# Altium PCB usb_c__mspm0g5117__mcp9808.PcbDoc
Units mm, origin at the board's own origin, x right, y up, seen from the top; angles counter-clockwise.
Board outline 68 x 40 mm, 2 copper layers (Top, Bottom), stack 0 mm thick; 35 components, 28 nets, 180 pads, 67 vias.
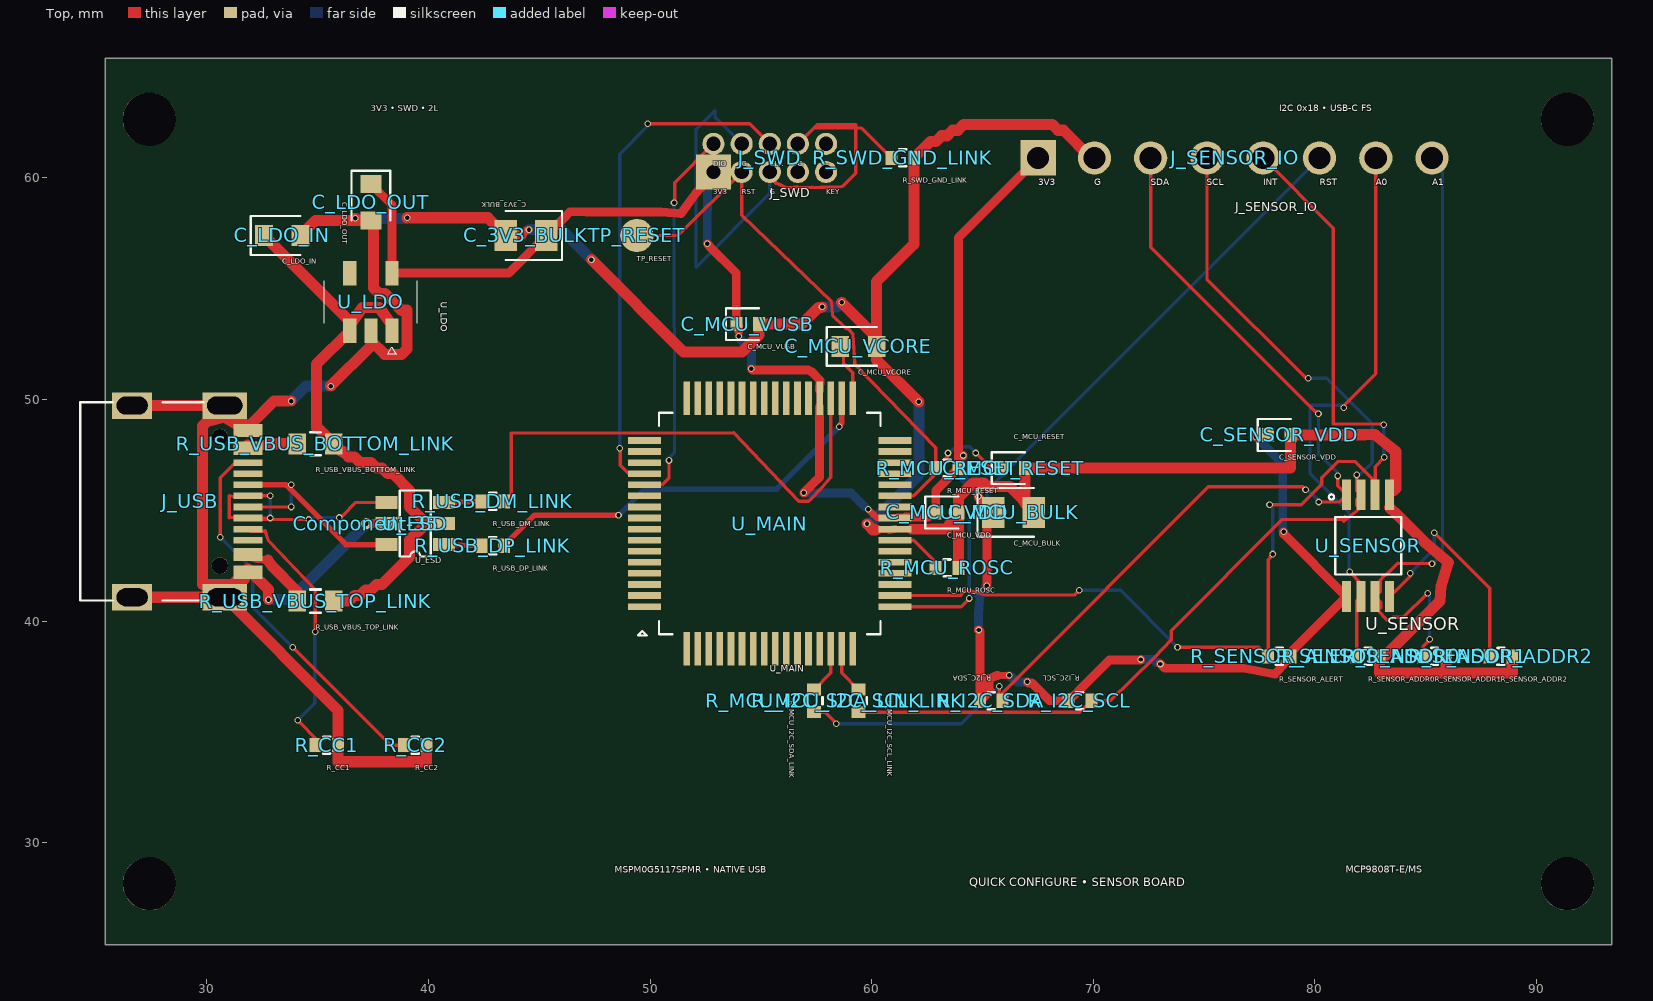
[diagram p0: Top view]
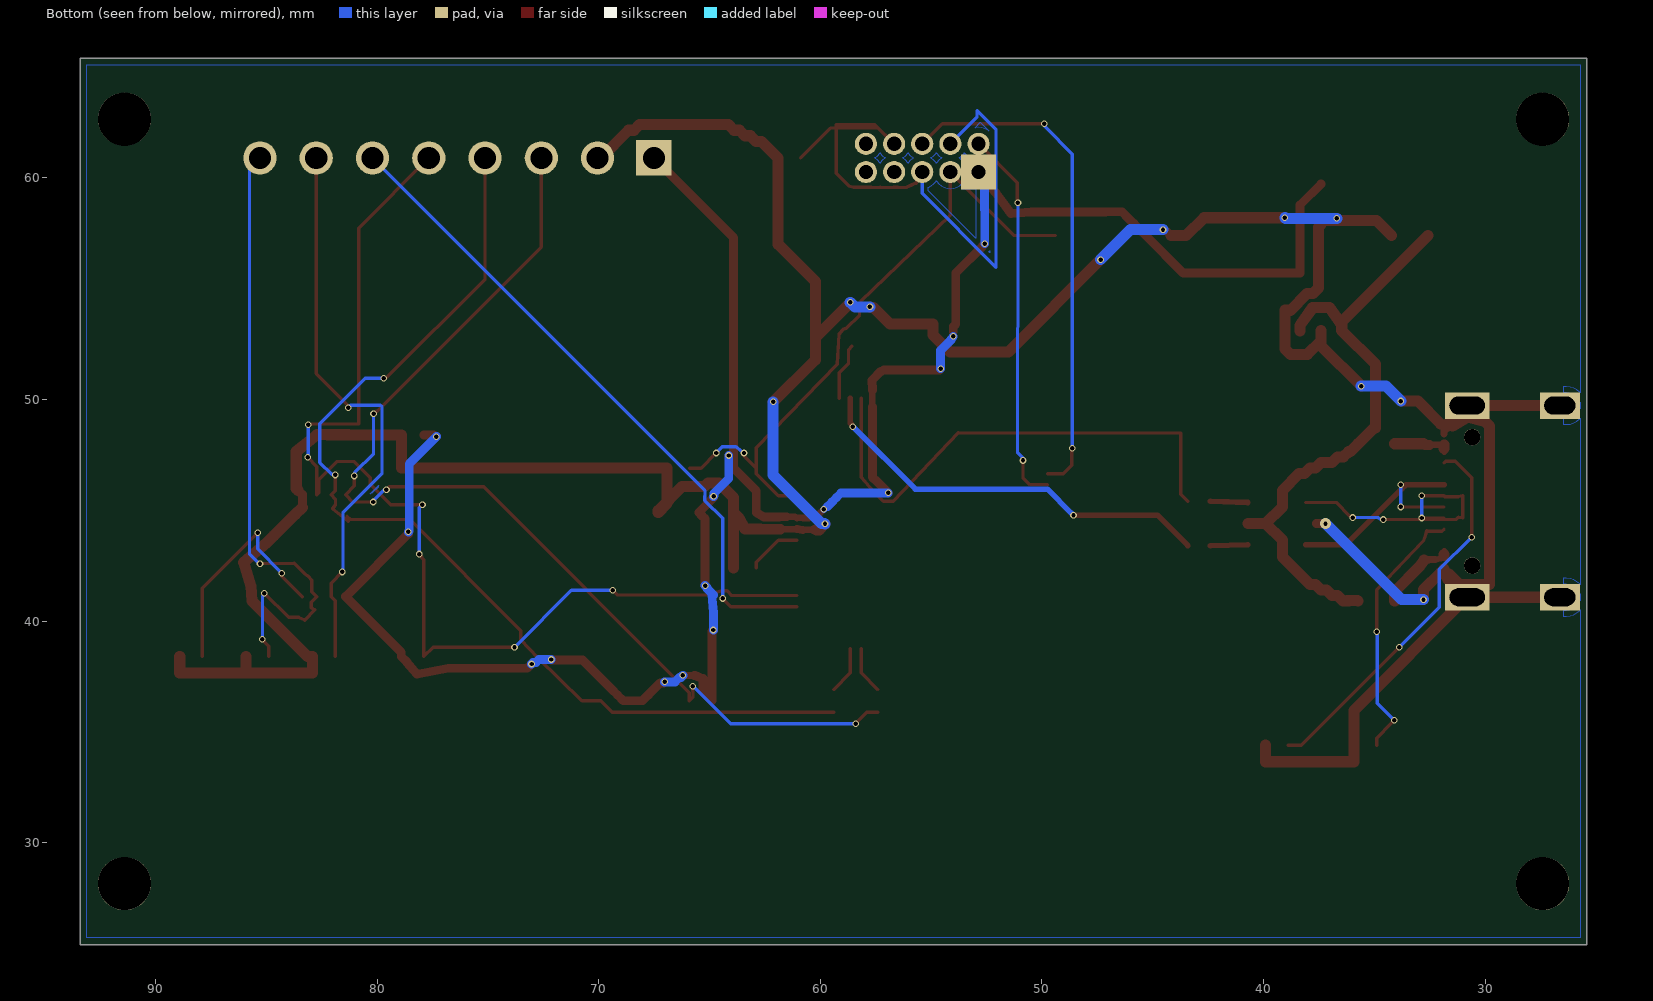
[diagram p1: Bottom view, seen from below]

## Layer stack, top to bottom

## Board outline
25.4,65.4 93.4,65.4 93.4,25.4 25.4,25.4

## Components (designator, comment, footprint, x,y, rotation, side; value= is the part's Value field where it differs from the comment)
C_3V3_BULK "" TSCIRCUIT-2.8500x1.4000mm 44.4,57.4 r180 top
C_LDO_IN "" TSCIRCUIT-2.4500x0.9500mm 33.4,57.4 r0 top
C_LDO_OUT "" TSCIRCUIT-0.9500x2.4500mm 37.4,58.9 r270 top
C_MCU_BULK "" TSCIRCUIT-2.8500x1.4000mm 66.4,44.9 r0 top
C_MCU_RESET "" TSCIRCUIT-1.5600x0.6400mm 66.4,46.9 r0 top
C_MCU_VCORE "" TSCIRCUIT-2.4500x0.9500mm 59.4,52.4 r0 top
C_MCU_VDD "" TSCIRCUIT-1.5600x0.6400mm 63.4,44.9 r0 top
C_MCU_VUSB "" TSCIRCUIT-1.5600x0.6400mm 54.4,53.4 r0 top
C_SENSOR_VDD "" TSCIRCUIT-1.5600x0.6400mm 78.4,48.4 r0 top
Component-35 "" TSCIRCUIT-0.5000x0.5000mm 37.2,44.4 r0 top
J_SENSOR_IO "" TSCIRCUIT-19.2800x1.5000mm 76.4,60.9 r0 top
J_SWD "" TSCIRCUIT-6.0800x2.2700mm 55.4,60.9 r0 top
J_USB "" TSCIRCUIT-6.7732x9.8502mm 29.112,45.4 r90 top
R_CC1 "" TSCIRCUIT-1.5600x0.6400mm 35.4,34.4 r0 top
R_CC2 "" TSCIRCUIT-1.5600x0.6400mm 39.4,34.4 r0 top
R_I2C_SCL "" TSCIRCUIT-1.5600x0.6400mm 69.4,36.4 r180 top
R_I2C_SDA "" TSCIRCUIT-1.5600x0.6400mm 65.4,36.4 r180 top
R_MCU_I2C_SCL_LINK "" TSCIRCUIT-0.6400x1.5600mm 59.4,36.4 r270 top
R_MCU_I2C_SDA_LINK "" TSCIRCUIT-0.6400x1.5600mm 57.4,36.4 r270 top
R_MCU_RESET "" TSCIRCUIT-1.5600x0.6400mm 63.4,46.9 r0 top
R_MCU_ROSC "" TSCIRCUIT-1.5600x0.6400mm 63.4,42.4 r0 top
R_SENSOR_ADDR0 "" TSCIRCUIT-1.5600x0.6400mm 82.4,38.4 r0 top
R_SENSOR_ADDR1 "" TSCIRCUIT-1.5600x0.6400mm 85.4,38.4 r0 top
R_SENSOR_ADDR2 "" TSCIRCUIT-1.5600x0.6400mm 88.4,38.4 r0 top
R_SENSOR_ALERT "" TSCIRCUIT-1.5600x0.6400mm 78.4,38.4 r0 top
R_SWD_GND_LINK "" TSCIRCUIT-1.5600x0.6400mm 61.4,60.9 r0 top
R_USB_DM_LINK "" TSCIRCUIT-1.5600x0.6400mm 42.9,45.4 r0 top
R_USB_DP_LINK "" TSCIRCUIT-1.5600x0.6400mm 42.9,43.4 r0 top
R_USB_VBUS_BOTTOM_LINK "" TSCIRCUIT-2.4500x0.9500mm 34.9,48 r0 top
R_USB_VBUS_TOP_LINK "" TSCIRCUIT-2.4500x0.9500mm 34.9,40.9 r0 top
TP_RESET "" TSCIRCUIT-1.5000x1.5000mm 49.4,57.4 r0 top
U_ESD "" TSCIRCUIT-3.6000x2.5000mm 39.4,44.4 r0 top
U_LDO "" TSCIRCUIT-2.5000x3.7000mm 37.4,54.4 r270 top
U_MAIN "" TSCIRCUIT-12.8000x12.8000mm 55.4,44.4 r0 top
U_SENSOR "" TSCIRCUIT-2.3562x5.9969mm 82.4,43.4 r0 top

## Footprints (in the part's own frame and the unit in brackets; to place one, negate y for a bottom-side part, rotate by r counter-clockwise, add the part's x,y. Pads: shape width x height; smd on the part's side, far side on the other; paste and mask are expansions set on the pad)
TSCIRCUIT-0.5000x0.5000mm [mm]
TSCIRCUIT-0.6400x1.5600mm [mm]
  rect 0.54x0.64 smd: 1(-0.51,0) 2(0.51,0)
  silkscreen extent -0.15,-0.38 0.15,0.38
TSCIRCUIT-0.9500x2.4500mm [mm]
  rect 0.8x0.95 smd: 1(-0.825,0) 2(0.825,0)
  silkscreen extent -1.43,-0.87 0.82,0.88
TSCIRCUIT-1.5000x1.5000mm [mm]
  round 1.5 smd: 1(0,0)
TSCIRCUIT-1.5600x0.6400mm [mm]
  rect 0.54x0.64 smd: 1(-0.51,0) 2(0.51,0)
  silkscreen extent -0.98,-0.72 0.51,0.72
TSCIRCUIT-2.3562x5.9969mm [mil]
  rect 15.98x55 smd: 1(-38.39,90.55) 2(-12.8,90.55) 3(12.8,90.55) 4(38.39,90.55) 5(38.39,-90.55) 6(12.8,-90.55) 7(-12.8,-90.55) 8(-38.39,-90.55)
  silkscreen extent -70,-51 59,91
TSCIRCUIT-2.4500x0.9500mm [mm]
  rect 0.8x0.95 smd: 1(-0.825,0) 2(0.825,0)
  silkscreen extent -1.42,-0.87 0.82,0.87
TSCIRCUIT-2.5000x3.7000mm [mm]
  rect 1.1x0.6 smd: 1(1.3,0.95) 2(1.3,0) 3(1.3,-0.95) 4(-1.3,-0.95) 5(-1.3,0.95)
  silkscreen extent -0.95,-2.1 2.35,2.1
TSCIRCUIT-2.8500x1.4000mm [mm]
  rect 1.025x1.4 smd: 1(-0.913,0) 2(0.913,0)
  silkscreen extent -1.63,-1.1 0.91,1.1
TSCIRCUIT-3.6000x2.5000mm [mm]
  rect 1x0.6 smd: 1(-1.3,-0.95) 2(-1.3,0) 3(-1.3,0.95) 4(1.3,0.95) 5(1.3,0) 6(1.3,-0.95)
  silkscreen extent -0.7,-1.49 0.7,1.49
TSCIRCUIT-6.0800x2.2700mm [mm]
  rect 1.6x1.6 hole 0.65: 1(-2.54,-0.635)
  round 1 hole 0.65: 2(-2.54,0.635) 3(-1.27,0.635) 4(0,0.635) 5(1.27,0.635) 6(2.54,0.635) 7(2.54,-0.635) 8(1.27,-0.635) 9(0,-0.635) 10(-1.27,-0.635)
TSCIRCUIT-6.7732x9.8502mm [mm]
  rect 0.3x1.3 smd: 1(-3.35,-2.737) 2(-3.05,-2.737) 3(-2.55,-2.737) 4(-2.25,-2.737) 5(-1.75,-2.737) 6(-1.25,-2.737) 7(-0.75,-2.737) 8(-0.25,-2.737) 9(0.25,-2.737) 10(0.75,-2.737) 11(1.25,-2.737) 12(1.75,-2.737) 13(2.55,-2.737) 14(2.25,-2.737) 15(3.35,-2.737) 16(3.05,-2.737)
  rect 1.2x2 hole 0.8 slot 1.6 at 90 deg: 17(-4.325,-1.693) 18(4.325,-1.693)
  rect 1.2x1.8 hole 0.8 slot 1.4 at 90 deg: 19(4.325,2.487) 20(-4.325,2.487)
  round 0.75 hole 0.75 unplated: NPTH-1(-2.9,-1.468) NPTH-2(2.9,-1.468)
  silkscreen extent -4.47,-0.75 4.47,4.83
TSCIRCUIT-12.8000x12.8000mm [mm]
  rect 1.5x0.3 smd: 1(-5.65,-3.75) 2(-5.65,-3.25) 3(-5.65,-2.75) 4(-5.65,-2.25) 5(-5.65,-1.75) 6(-5.65,-1.25) 7(-5.65,-0.75) 8(-5.65,-0.25) 9(-5.65,0.25) 10(-5.65,0.75) 11(-5.65,1.25) 12(-5.65,1.75) 13(-5.65,2.25) 14(-5.65,2.75) 15(-5.65,3.25) 16(-5.65,3.75) 33(5.65,3.75) 34(5.65,3.25) 35(5.65,2.75) 36(5.65,2.25) 37(5.65,1.75) 38(5.65,1.25) 39(5.65,0.75) 40(5.65,0.25) 41(5.65,-0.25) 42(5.65,-0.75) 43(5.65,-1.25) 44(5.65,-1.75) 45(5.65,-2.25) 46(5.65,-2.75) 47(5.65,-3.25) 48(5.65,-3.75)
  rect 0.3x1.5 smd: 17(-3.75,5.65) 18(-3.25,5.65) 19(-2.75,5.65) 20(-2.25,5.65) 21(-1.75,5.65) 22(-1.25,5.65) 23(-0.75,5.65) 24(-0.25,5.65) 25(0.25,5.65) 26(0.75,5.65) 27(1.25,5.65) 28(1.75,5.65) 29(2.25,5.65) 30(2.75,5.65) 31(3.25,5.65) 32(3.75,5.65) 49(3.75,-5.65) 50(3.25,-5.65) 51(2.75,-5.65) 52(2.25,-5.65) 53(1.75,-5.65) 54(1.25,-5.65) 55(0.75,-5.65) 56(0.25,-5.65) 57(-0.25,-5.65) 58(-0.75,-5.65) 59(-1.25,-5.65) 60(-1.75,-5.65) 61(-2.25,-5.65) 62(-2.75,-5.65) 63(-3.25,-5.65) 64(-3.75,-5.65)
  silkscreen extent -5.95,-5.05 5,5
TSCIRCUIT-19.2800x1.5000mm [mm]
  rect 1.6x1.6 hole 1: 1(-8.89,0)
  round 1.5 hole 1: 2(-6.35,0) 3(-3.81,0) 4(-1.27,0) 5(1.27,0) 6(3.81,0) 7(6.35,0) 8(8.89,0)

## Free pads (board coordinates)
  round 2.4 hole 2.4 unplated: NPTH-3(27.4,28.15) NPTH-4(91.4,28.15) NPTH-5(27.4,62.65) NPTH-6(91.4,62.65)

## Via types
v1: diameter 0.3, hole 0.2, Top to Bottom, 66 vias
v2: diameter 0.5, hole 0.2, Top to Bottom, 1 vias

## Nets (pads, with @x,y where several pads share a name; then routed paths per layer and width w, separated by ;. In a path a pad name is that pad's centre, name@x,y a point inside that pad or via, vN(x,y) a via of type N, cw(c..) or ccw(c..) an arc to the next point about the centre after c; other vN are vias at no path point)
".J_SWD > .pin2 to .U_MAIN > .pin12": J_SWD.2 U_MAIN.12 | length 17.2
  Top w0.15: U_MAIN.12 49.759,46.159 50.54,46.159 50.853,46.472 v1(50.853,47.247) ; v1(51.08,58.875) 51.105,58.856 51.105,59.012 51.105,59.78 J_SWD.2
  Bottom w0.15: v1(50.853,47.247) 50.793,47.307 51.102,47.616 v1(51.08,58.875)
".J_SWD > .pin4 to .U_MAIN > .pin13": J_SWD.4 U_MAIN.13 | length 23.1
  Top w0.15: v1(48.63,47.806) 48.64,47.796 48.64,47.769 48.656,47.753 48.656,47.026 49.032,46.65 U_MAIN.13 ; v1(49.886,62.448) 54.487,62.448 J_SWD.4
  Bottom w0.15: v1(48.63,47.806) 48.63,61.072 49.855,62.297 49.855,62.417 v1(49.886,62.448)
".U_MAIN > .pin42 to .R_MCU_ROSC > .pin1": R_MCU_ROSC.1 U_MAIN.42 | length 2.5
  Top w0.15: U_MAIN.42 61.89,43.65 62.89,42.65 R_MCU_ROSC.1
GND: C_3V3_BULK.2 C_LDO_IN.2 C_LDO_OUT.2 C_MCU_BULK.2 C_MCU_RESET.2 C_MCU_VCORE.2 C_MCU_VDD.2 C_MCU_VUSB.2 C_SENSOR_VDD.2 J_SENSOR_IO.2 J_USB.1 J_USB.2 J_USB.15 J_USB.16 J_USB.17 J_USB.18 J_USB.19 J_USB.20 R_CC1.2 R_CC2.2 R_MCU_ROSC.2 R_SENSOR_ADDR0.2 R_SENSOR_ADDR1.2 R_SENSOR_ADDR2.2 R_SWD_GND_LINK.2 U_ESD.2 U_LDO.2 U_MAIN.41 U_SENSOR.4 | length 177.8
  Top w0.275: J_USB.15@31.467,48.8 31.8,48.6 J_USB.16 ; J_USB.1@31.624,42.125 J_USB.2
  Top w0.3: J_USB.1@31.699,41.9 J_USB.1 J_USB.1@31.849,42.2 ; J_USB.15@31.699,48.9 J_USB.15 ; J_USB.2 J_USB.1@31.999,42.2 ; J_USB.16@31.849,48.6 J_USB.15 ; J_USB.15@31.999,48.9 J_USB.15 ; 60.3,44.12 60.425,44.12 60.55,44.12 60.675,44.12 U_MAIN.41@60.796,44.111 ; U_MAIN.41 61.144,44.15 61.238,44.15 61.331,44.15 61.425,44.15 61.519,44.15 61.613,44.15 61.706,44.15 61.8,44.15
  Top w0.325: J_USB.16 J_USB.16@31.849,48.6 ; v1@44.396,57.621 44.502,57.621 v1(44.535,57.666)
  Top w0.375: 44.175,57.4 v1@44.396,57.621 ; U_MAIN.41@60.796,44.111 U_MAIN.41
  Top w0.4: 37.2,44.4 U_ESD.2@37.6,44.4 ; 60.175,44.12 60.3,44.12
  Top w0.406: U_SENSOR.4@83.375,45.129 83.375,45.414 U_SENSOR.4 83.578,45.903
  Top w0.475: 61.8,44.15 62.253,44.15 62.707,44.15
  Top w0.5: J_USB.20 J_USB.17 ; J_USB.19 J_USB.18 ; J_USB.18 30.874,49.725 31.474,49.125 31.699,48.9 ; J_USB.15@31.467,48.8 31.133,49 30.8,49.2 30,49 29.8,48.8 29.8,41.65 31.15,41.65 J_USB.1@31.624,42.124 ; 31.699,41.9 31.474,41.675 30.874,41.075 J_USB.17 35.91,35.971 R_CC1.2 35.91,33.65 39.91,33.65 R_CC2.2 ; J_USB.1@31.849,42.2 J_USB.2 ; J_USB.1@31.999,42.2 32.778,41.421 v1(32.778,40.965) ; 31.999,48.9 33.028,49.929 v1(33.802,49.929) ; C_LDO_IN.2 34.9,58.075 C_LDO_OUT.2 ; v1(35.586,50.6) 37.4,52.414 U_LDO.2 37.4,52.65 38.025,52.025 38.775,52.025 39.025,52.275 39.025,54.025 38.775,54.025 38.025,54.775 37.775,54.775 37.525,55.025 37.525,57.775 37.4,57.9 C_LDO_OUT.2 ; v1(36.694,58.171) 36.781,58.084 36.9,58.084 36.91,58.075 C_LDO_OUT.2 ; v1(39.034,58.199) 42.688,58.199 C_3V3_BULK.2 43.831,57.4 44.175,57.4 ; v1(47.353,56.313) 51.516,52.15 54.15,52.15 54.91,52.91 C_MCU_VUSB.2 55.398,53.4 55.885,53.4 56.373,53.4 56.86,53.4 57.108,53.647 57.355,53.895 57.602,54.142 57.725,54.142 v1(57.76,54.177) ; v1(58.647,54.381) 60.225,52.803 C_MCU_VCORE.2 ; v1(59.788,44.388) 60.049,44.118 60.175,44.12 ; v1(62.126,49.891) 60.225,51.792 C_MCU_VCORE.2 ; 62.707,44.15 63.4,44.15 63.66,44.65 C_MCU_VDD.2 ; R_MCU_ROSC.2 C_MCU_VDD.2 ; J_SENSOR_IO.2 69.9,60.9 68.65,62.15 68.4,62.15 68.15,62.4 64.15,62.4 63.9,62.15 63.65,62.15 63.4,61.9 63.15,61.9 62.9,61.65 62.65,61.65 62.65,61.64 62.579,61.569 62.244,61.234 R_SWD_GND_LINK.2 61.91,57.006 60.225,55.321 60.225,54.834 60.225,54.347 60.225,53.86 60.225,53.374 60.225,52.887 C_MCU_VCORE.2 ; U_SENSOR.4@83.375,45.129 83.698,44.809 84.02,44.489 84.342,44.169 84.665,43.85 84.987,43.53 86.025,42.65 85.697,41.586 85.65,40.9 83.15,38.4 R_SENSOR_ADDR0.2 82.91,37.65 85.91,37.65 ; 83.578,45.903 83.65,45.975 83.65,47.65 82.72,48.41 82.244,48.408 81.768,48.407 81.291,48.406 80.815,48.405 80.339,48.404 79.863,48.402 79.386,48.401 C_SENSOR_VDD.2 78.91,46.9 74.069,46.9 73.592,46.9 73.115,46.9 72.637,46.9 72.16,46.9 71.683,46.9 71.205,46.9 70.728,46.9 70.251,46.9 69.774,46.9 69.296,46.9 68.819,46.9 68.342,46.9 67.865,46.9 67.387,46.9 C_MCU_RESET.2 66.91,45.303 C_MCU_BULK.2 67.312,44.988 66.233,46.067 65.233,46.067 65.067,46.233 64.567,46.233 63.91,45.577 C_MCU_VDD.2 ; R_SENSOR_ADDR2.2 88.91,37.65 85.91,37.65 ; 85.91,37.65 R_SENSOR_ADDR1.2 85.91,37.65
  Bottom w0.5: v1(32.778,40.965) 33.765,40.965 37.2,44.4 ; v1(33.802,49.929) 33.892,50.019 34.183,50.31 34.473,50.6 34.844,50.6 35.215,50.6 v1(35.586,50.6) ; v1(36.694,58.171) 39.006,58.171 v1(39.034,58.199) ; v1(44.535,57.666) 46,57.666 v1(47.353,56.313) ; v1(57.76,54.177) 58.443,54.177 v1(58.647,54.381) ; v1(59.788,44.388) 59.81,44.41 59.94,44.41 62.126,46.596 v1(62.126,49.891)
MAIN_RESET: C_MCU_RESET.1 J_SWD.10 R_MCU_RESET.1 TP_RESET.1 U_MAIN.38 | length 29.3
  Top w0.15: TP_RESET.1 51.265,57.4 J_SWD.10 54.13,58.304 58.189,54.401 58.23,53.809 58.833,53.214 58.97,53.168 59.155,52.938 59.231,51.596 62.89,47.816 R_MCU_RESET.1 63.502,47.512 v1(63.445,47.585) ; U_MAIN.38 61.889,45.65 62.89,46.651 R_MCU_RESET.1@62.89,46.9 ; v1(64.699,47.585) 64.719,47.565 65.384,46.9 C_MCU_RESET.1
  Bottom w0.15: v1(63.445,47.585) 63.622,47.705 ; 63.623,47.705 63.77,47.852 63.811,47.86 64.432,47.86 v1(64.699,47.585)
MCU_I2C_SCL_LOCAL: R_MCU_I2C_SCL_LINK.1 U_MAIN.50 | length 2.2
  Top w0.15: U_MAIN.50 58.65,37.66 R_MCU_I2C_SCL_LINK.1
MCU_I2C_SDA_LOCAL: R_MCU_I2C_SDA_LINK.1 U_MAIN.51 | length 2.2
  Top w0.15: R_MCU_I2C_SDA_LINK.1 58.15,37.66 U_MAIN.51
MSPM0_VCORE: C_MCU_VCORE.1 U_MAIN.32 | length 2.6
  Top w0.15: C_MCU_VCORE.1 58.725,52.25 58.725,51.624 59.15,51.199 U_MAIN.32
SENSOR_ADDR0: J_SENSOR_IO.7 R_SENSOR_ADDR0.1 U_SENSOR.7 | length 25.8
  Top w0.15: v1(81.308,49.63) 81.322,49.644 81.322,49.742 82.75,51.17 J_SENSOR_IO.7 ; v1(81.57,42.216) 82.075,41.711 U_SENSOR.7 81.89,40.915 R_SENSOR_ADDR0.1
  Bottom w0.15: v1(81.308,49.63) 81.206,49.732 79.851,49.732 79.779,49.66 79.779,46.664 81.537,44.906 81.537,42.371 81.537,42.249 v1(81.57,42.216)
SENSOR_ADDR1: J_SENSOR_IO.8 R_SENSOR_ADDR1.1 U_SENSOR.6 | length 29
  Top w0.15: R_SENSOR_ADDR1.1 84.89,38.857 85.097,39.064 85.097,39.1 v1(85.178,39.181) ; v1(85.088,41.257) 83.997,40.166 83.542,40.166 83.266,40.04 82.806,40.505 82.967,40.588 82.967,40.858 U_SENSOR.6 82.946,41.321 82.946,41.486 82.946,41.575 82.958,41.838 83.106,42.016 83.278,42.133 83.748,42.602 v1(85.286,42.592)
  Bottom w0.15: v1(85.088,41.257) 85.118,41.227 85.118,41.155 85.178,41.095 v1(85.178,39.181) ; v1(85.286,42.592) 85.348,42.617 85.763,43.032 85.763,43.096 85.763,60.427 J_SENSOR_IO.8
SENSOR_ADDR2: R_SENSOR_ADDR2.1 U_SENSOR.5 | length 10.3
  Top w0.15: U_SENSOR.5 84.3,42.025 v1(84.3,42.159) ; v1(85.394,43.985) 85.481,43.898 87.89,41.489 R_SENSOR_ADDR2.1
  Bottom w0.15: v1(84.3,42.159) 84.322,42.181 85.394,43.253 v1(85.394,43.985)
SENSOR_INT: J_SENSOR_IO.5 R_SENSOR_ALERT.1 U_MAIN.47 U_SENSOR.3 | length 50.9
  Top w0.15: U_MAIN.47 63.992,41.15 64.21,41.368 64.447,41.368 65.112,41.177 69.159,41.177 69.3,41.318 v1(69.366,41.384) ; v1(73.801,38.812) 77.478,38.812 R_SENSOR_ALERT.1 77.89,42.773 77.98,42.863 77.98,42.909 v1(78.094,43.023) ; J_SENSOR_IO.5 80.837,57.733 80.837,48.895 83.086,48.895 83.086,48.887 v1(83.107,48.866) ; v1(77.956,45.254) 79.395,45.254 80.314,46.173 80.314,46.476 81.036,47.198 81.829,47.198 82.623,46.405 82.623,45.802 U_SENSOR.3 82.725,46.974 v1(83.137,47.386)
  Bottom w0.15: v1(69.366,41.384) 71.229,41.384 73.798,38.815 v1(73.801,38.812) ; v1(77.956,45.254) 77.982,45.228 77.982,45.226 78.094,45.114 v1(78.094,43.023) ; v1(83.107,48.866) 83.107,47.617 83.107,47.452 v1(83.137,47.386)
SENSOR_RESET: J_SENSOR_IO.6 U_MAIN.48 | length 29.9
  Top w0.15: U_MAIN.48 64.033,40.65 v1@64.398,41.016 ; v1@64.399,41.016 v1(64.403,41.02)
  Bottom w0.15: v1(64.403,41.02) 64.403,44.636 65.208,45.437 65.207,45.894 J_SENSOR_IO.6
SENSOR_SCL: J_SENSOR_IO.4 R_I2C_SCL.1 R_MCU_I2C_SCL_LINK.2 U_SENSOR.2 | length 47
  Top w0.15: R_MCU_I2C_SCL_LINK.2 69.4,35.89 R_I2C_SCL.1 70.758,36.4 72.757,38.337 73.517,39.159 73.517,39.571 78.529,44.583 81.207,44.583 81.363,44.739 81.306,44.508 82.013,45.065 81.88,45.245 81.88,45.267 81.88,45.505 U_SENSOR.2 81.889,45.886 v1(81.889,46.594) ; J_SENSOR_IO.4 75.13,55.429 79.564,50.995 79.663,50.995 v1(79.706,50.952)
  Bottom w0.15: v1(79.706,50.952) 80.534,50.952 82.587,48.899 82.587,47.153 82.055,46.621 81.916,46.621 v1(81.889,46.594)
SENSOR_SDA: J_SENSOR_IO.3 R_I2C_SDA.1 R_MCU_I2C_SDA_LINK.2 U_SENSOR.1 | length 49.1
  Top w0.15: R_MCU_I2C_SDA_LINK.2 57.905,35.89 58.4,35.395 v1(58.4,35.37) ; v1(65.756,37.06) 65.748,36.562 R_I2C_SDA.1 65.91,36.77 75.194,46.054 79.442,46.054 ; J_SENSOR_IO.3 72.59,56.88 80,49.469 80.046,49.469 v1(80.163,49.352) ; 79.443,46.055 79.452,46.055 v1(79.58,45.927) ; v1(80.179,45.371) 81.096,45.371 U_SENSOR.1 81.028,46.097 v1(81.028,46.548)
  Bottom w0.15: v1(58.4,35.37) 64.05,35.37 65.74,37.06 v1(65.756,37.06) ; v1(79.58,45.927) 79.686,45.927 80.14,45.473 80.14,45.41 v1(80.179,45.371) ; v1(80.163,49.352) 80.163,47.555 81.013,46.705 81.013,46.563 v1(81.028,46.548)
swd-ground-1-to-2: J_SWD.3 J_SWD.5 J_SWD.9 R_SWD_GND_LINK.1 | length 29.8
  Top w0.15: J_SWD.9 55.675,59.765 55.7,59.765 55.91,59.667 56.092,59.578 56.3,59.569 56.501,59.575 56.7,59.575 56.9,59.568 57.3,59.578 57.499,59.567 57.7,59.575 57.9,59.575 58.1,59.573 58.505,59.575 58.717,59.638 59.277,60.198 59.277,62.405 57.54,62.405 J_SWD.5 57.382,62.247 59.375,62.247 59.543,62.247 R_SWD_GND_LINK.1
  Bottom w0.15: J_SWD.3 52.932,62.733 52.932,63.044 52.068,62.18 52.071,55.966 55.401,59.299 J_SWD.9
usb-dm-device: R_USB_DM_LINK.1 U_ESD.4 | length 1.7
  Top w0.25: U_ESD.4 R_USB_DM_LINK.1
usb-dm-mcu: R_USB_DM_LINK.2 U_MAIN.30 | length 23
  Top w0.15: R_USB_DM_LINK.2 43.732,45.722 43.732,48.487 53.772,48.493 56.7,45.4 57.15,45.4 57.787,46.069 58.15,46.495 U_MAIN.30
usb-dm-port-tie: J_USB.7 J_USB.9 U_ESD.3 | length 12.3
  Top w0.15: J_USB.7 v1(32.85,44.65) ; v1(32.85,45.65) J_USB.9 31.816,45.617 31.199,45.617 31.013,45.65 31.013,44.65 31.199,44.682 31.29,44.591 v1(34.59,44.581) ; v1(35.977,44.671) 36.058,44.739 36.103,44.739 36.715,45.35 U_ESD.3
  Bottom w0.15: v1(32.85,44.65) v1(32.85,45.65) ; v1(34.59,44.581) 34.618,44.609 34.758,44.609 34.814,44.665 v1(35.977,44.671)
usb-dp-device: R_USB_DP_LINK.1 U_ESD.6 | length 1.7
  Top w0.25: U_ESD.6 R_USB_DP_LINK.1
usb-dp-mcu: R_USB_DP_LINK.2 U_MAIN.31 | length 18.7
  Top w0.25: R_USB_DP_LINK.2 44.791,44.781 v1(48.574,44.781) ; v1(58.531,48.769) 58.559,48.797 58.559,48.838 58.65,48.928 U_MAIN.31
  Bottom w0.25: v1(48.574,44.781) 48.648,44.855 48.655,44.855 49.75,45.951 49.95,45.951 55.713,45.951 v1(58.531,48.769)
usb-dp-port-tie: J_USB.8 J_USB.10 U_ESD.1 | length 12.3
  Top w0.15: J_USB.8 v1(33.8,45.15) ; J_USB.10 v1(33.8,46.15)
  Top w0.25: J_USB.10 33.562,46.15 33.77,45.953 36.267,43.454 U_ESD.1
  Bottom w0.15: v1(33.8,45.15) v1(33.8,46.15)
USB_CC1: J_USB.6 R_CC1.1 | length 12
  Top w0.15: J_USB.6 31.943,44.056 32.553,44.056 32.634,44.069 32.69,43.875 32.781,43.613 34.89,41.404 v1(34.89,39.52) ; v1(34.09,35.52) 34.232,35.378 34.89,34.72 R_CC1.1
  Bottom w0.15: v1(34.09,35.52) 34.86,36.29 34.86,39.449 34.86,39.49 v1(34.89,39.52)
USB_CC2: J_USB.12 R_CC2.1 | length 17.4
  Top w0.15: v1(30.606,43.779) 30.606,46.476 31.349,47.219 31.78,47.215 J_USB.12 ; v1(33.873,38.825) 33.944,38.754 38.298,34.4 R_CC2.1
  Bottom w0.15: v1(30.606,43.779) 30.645,43.74 30.656,43.74 32.07,42.326 32.07,40.628 v1(33.873,38.825)
USB_VBUS_BOTTOM_LOCAL: J_USB.13 J_USB.14 R_USB_VBUS_BOTTOM_LINK.1 | length 2.5
  Top w0.3: J_USB.14 J_USB.14@31.849,47.8 ; J_USB.13 J_USB.13@32.499,47.95
  Top w0.437: 32.72,47.95 32.769,48
  Top w0.45: 32.499,47.95 32.72,47.95
  Top w0.475: J_USB.13@31.849,47.8 J_USB.13
  Top w0.5: 32.769,48 33.205,48 33.64,48 R_USB_VBUS_BOTTOM_LINK.1
USB_VBUS_TOP_LOCAL: J_USB.3 J_USB.4 R_USB_VBUS_TOP_LINK.1 | length 3.6
  Top w0.275: J_USB.3 J_USB.3@32.243,42.777
  Top w0.3: J_USB.3 31.849,43 J_USB.4
  Top w0.325: J_USB.3@32.243,42.777 32.556,42.771
  Top w0.35: 32.556,42.771 32.759,42.744
  Top w0.5: 32.759,42.744 32.962,42.454 34.075,41.34 R_USB_VBUS_TOP_LINK.1
VBUS5: C_LDO_IN.1 R_USB_VBUS_BOTTOM_LINK.2 R_USB_VBUS_TOP_LINK.2 U_ESD.5 U_LDO.1 U_LDO.3 | length 29.2
  Top w0.5: C_LDO_IN.1 36.45,53.525 U_LDO.3 ; R_USB_VBUS_TOP_LINK.2 35.751,40.926 36.232,40.926 36.176,40.926 36.15,40.9 36.4,40.9 36.65,41.15 36.9,41.15 37.15,41.4 37.4,41.4 37.65,41.65 37.9,41.65 39.15,42.9 39.15,43.65 39.9,44.4 ; U_LDO.1 38.35,53.347 37.775,54.15 37.025,54.15 36.468,53.371 36.468,53.118 U_LDO.3 ; U_LDO.3 34.951,51.601 34.951,48.707 35.018,48.707 R_USB_VBUS_BOTTOM_LINK.2 36.077,47.648 36.079,47.65 36.15,47.65 36.4,47.4 36.65,47.4 36.9,47.15 37.4,47.15 37.65,46.9 37.9,46.9 38.15,46.65 38.4,46.65 39.15,45.9 39.15,45.15 39.9,44.4 ; 39.9,44.4 U_ESD.5 39.9,44.4
VCC_3V3: C_3V3_BULK.1 C_LDO_OUT.1 C_MCU_BULK.1 C_MCU_VDD.1 C_MCU_VUSB.1 C_SENSOR_VDD.1 J_SENSOR_IO.1 J_SWD.1 R_I2C_SCL.2 R_I2C_SDA.2 R_MCU_RESET.2 R_SENSOR_ALERT.2 U_LDO.5 U_MAIN.29 U_MAIN.40 U_SENSOR.8 | length 106.6
  Top w0.3: v1(54,52.848) 54,53.069 ; U_MAIN.29@57.65,49.655 U_MAIN.29 U_MAIN.29@57.65,50.424 ; v1(59.839,45.038) 60.036,44.85 60.234,44.661 ; U_MAIN.40@60.778,44.654 U_MAIN.40
  Top w0.306: U_MAIN.40 61.162,44.705 U_MAIN.40@61.509,44.704
  Top w0.312: 60.234,44.661 U_MAIN.40@60.506,44.657
  Top w0.321: U_MAIN.40@60.506,44.657 U_MAIN.40@60.778,44.654
  Top w0.325: 65.677,37.549 65.939,37.547 v1(66.202,37.546)
  Top w0.387: U_MAIN.40@61.509,44.704 61.856,44.703
  Top w0.4: C_LDO_OUT.1 38.35,58.775 U_LDO.5 43.613,55.7 C_3V3_BULK.1 45.58,57.668 45.848,57.935 46.116,58.203 46.384,58.471 46.756,58.469 47.129,58.468 47.502,58.466 47.874,58.465 48.247,58.463 48.62,58.462 48.992,58.46 49.365,58.458 49.738,58.457 50.11,58.455 50.483,58.454 51.4,58.4 52.045,59.286 52.317,59.564 52.59,59.842 52.862,60.121 J_SWD.1 ; v1(52.581,57.027) 52.678,56.93 52.678,56.92 53.89,55.708 C_MCU_VUSB.1 54,53.29 54,53.069 ; v1(54.572,51.384) 54.622,51.334 54.627,51.329 54.983,51.329 55.339,51.329 55.695,51.329 56.051,51.329 56.407,51.329 56.763,51.329 57.119,51.329 57.267,51.267 57.667,50.867 U_MAIN.29@57.65,50.424 ; v1(56.937,45.783) 56.988,45.834 56.988,45.836 57.209,46.057 57.429,46.278 57.65,46.498 57.65,46.893 57.65,47.288 57.65,47.682 57.65,48.077 57.65,48.472 57.65,48.866 57.65,49.261 U_MAIN.29@57.65,49.655 ; 61.856,44.703 62.203,44.701 62.55,44.7 C_MCU_VDD.1 62.89,45.88 R_MCU_RESET.2 ; v1(64.13,47.47) 64.006,47.363 63.998,47.363 63.91,47.275 R_MCU_RESET.2 ; v1(64.818,45.628) 64.824,45.564 C_MCU_BULK.1 65.344,44.756 65.2,44.612 65.2,44.235 65.2,43.859 65.2,43.482 65.2,43.106 65.2,42.73 65.2,42.353 65.2,41.976 v1(65.2,41.6) ; v1(64.825,39.597) 64.89,39.532 64.89,39.4 64.89,39.025 64.89,38.65 64.89,38.275 64.89,37.9 64.89,37.525 64.89,37.15 64.89,36.775 R_I2C_SDA.2 65.117,36.627 65.343,36.853 65.3,36.8 65.3,37.4 65.677,37.549 ; v1(67.027,37.254) 67.075,37.206 67.224,37.206 67.493,36.937 67.761,36.669 68.03,36.4 68.317,36.4 68.603,36.4 R_I2C_SCL.2 69.154,36.664 69.417,36.927 69.681,37.191 69.945,37.455 70.209,37.719 70.472,37.982 70.736,38.246 71.083,38.246 71.43,38.246 71.777,38.246 72.124,38.246 v1(72.142,38.264) ; J_SENSOR_IO.1 63.914,57.3 R_MCU_RESET.2 ; v1(73.032,38.062) 73.223,37.871 73.62,37.871 74.017,37.871 74.414,37.871 74.81,37.871 75.207,37.871 75.604,37.871 76,37.871 76.397,37.871 76.794,37.871 78.2,37.6 78.645,38.135 R_SENSOR_ALERT.2 78.91,38.585 U_SENSOR.8 78.593,43.932 v1(78.593,44.026) ; v1(77.325,48.325) 77.362,48.362 77.406,48.362 77.444,48.4 C_SENSOR_VDD.1
  Bottom w0.325: 59.677,45.165 59.708,45.165 v1(59.839,45.038)
  Bottom w0.4: v1(52.581,57.027) 52.584,59.989 J_SWD.1 ; v1(54,52.848) 54.099,52.701 54.099,52.687 54.335,52.45 54.572,52.213 54.572,51.937 54.572,51.66 v1(54.572,51.384) ; v1(56.937,45.783) 57.292,45.783 57.646,45.782 58.001,45.781 58.355,45.78 58.71,45.779 59.064,45.778 59.269,45.574 59.473,45.37 59.677,45.165 ; v1(64.13,47.47) 64.13,46.434 64.799,45.765 64.799,45.654 v1(64.818,45.628) ; v1(64.825,39.597) 64.825,39.992 64.825,40.387 64.9,41.2 64.825,41.177 64.973,41.325 65.121,41.473 65.121,41.521 v1(65.2,41.6) ; v1(66.202,37.546) 66.295,37.453 66.36,37.453 66.56,37.254 66.793,37.254 v1(67.027,37.254) ; v1(72.142,38.264) 72.422,38.264 72.703,38.264 72.836,38.131 72.963,38.131 v1(73.032,38.062) ; v1(77.325,48.325) 78.553,47.097 78.553,44.085 78.553,44.066 v1(78.593,44.026)
pads on no net: J_SWD.6 J_SWD.7 J_SWD.8 J_USB.5 J_USB.11 J_USB.NPTH-1 J_USB.NPTH-2 U_LDO.4 U_MAIN.1 U_MAIN.2 U_MAIN.3 U_MAIN.4 U_MAIN.5 U_MAIN.6 U_MAIN.7 U_MAIN.8 U_MAIN.9 U_MAIN.10 U_MAIN.11 U_MAIN.14 U_MAIN.15 U_MAIN.16 U_MAIN.17 U_MAIN.18 U_MAIN.19 U_MAIN.20 U_MAIN.21 U_MAIN.22 U_MAIN.23 U_MAIN.24 U_MAIN.25 U_MAIN.26 U_MAIN.27 U_MAIN.28 U_MAIN.33 U_MAIN.34 U_MAIN.35 U_MAIN.36 U_MAIN.37 U_MAIN.39 U_MAIN.43 U_MAIN.44 U_MAIN.45 U_MAIN.46 U_MAIN.49 U_MAIN.52 U_MAIN.53 U_MAIN.54 U_MAIN.55 U_MAIN.56 U_MAIN.57 U_MAIN.58 U_MAIN.59 U_MAIN.60 U_MAIN.61 U_MAIN.62 U_MAIN.63 U_MAIN.64
copper on no net:
  other v2: 37.2,44.4

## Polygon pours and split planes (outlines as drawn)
GND on Bottom (solid): 93.1,65.1 25.7,65.1 25.7,50.296 25.725,50.326 25.854,50.432 26.001,50.51 26.16,50.559 26.326,50.575 26.476,50.575 26.476,50.325 26.326,50.325 26.209,50.314 26.096,50.279 25.993,50.224 25.902,50.149 25.827,50.058 25.772,49.955 25.747,49.875 25.7,49.875 25.7,49.575 25.747,49.575 25.772,49.496 25.827,49.392 25.902,49.301 25.993,49.226 26.096,49.171 26.209,49.137 26.326,49.125 26.476,49.125 26.476,48.875 26.326,48.875 26.16,48.891 26.001,48.94 25.854,49.018 25.725,49.124 25.7,49.154 25.7,41.646 25.725,41.676 25.854,41.782 26.001,41.86 26.16,41.909 26.326,41.925 26.476,41.925 26.476,41.675 26.326,41.675 26.209,41.663 26.096,41.629 25.993,41.574 25.902,41.499 25.827,41.408 25.772,41.304 25.747,41.225 25.7,41.225 25.7,40.925 25.747,40.925 25.772,40.845 25.827,40.742 25.902,40.651 25.993,40.576 26.096,40.521 26.209,40.486 26.326,40.475 26.476,40.475 26.476,40.225 26.326,40.225 26.16,40.241 26.001,40.29 25.854,40.368 25.725,40.474 25.7,40.504 25.7,25.7 93.1,25.7
GND on Bottom (solid): 52.777,62.5 52.4,62.123 52.443,62.159 52.573,62.228 52.714,62.271 52.86,62.285 53.005,62.271
GND on Bottom (solid): 53.495,61.14 53.484,61.118 53.399,61.015 53.591,61.015 53.506,61.118
GND on Bottom (solid): 53.61,60.996 53.61,60.804 53.713,60.889 53.735,60.9 53.713,60.911
GND on Bottom (solid): 57.305,61.14 57.294,61.118 57.2,61.005 57.087,60.911 57.065,60.9 57.087,60.889 57.2,60.795 57.294,60.682 57.305,60.66 57.316,60.682 57.41,60.795 57.523,60.889 57.545,60.9 57.523,60.911 57.41,61.005 57.316,61.118
GND on Bottom (solid): 56.035,61.14 56.024,61.118 55.93,61.005 55.817,60.911 55.795,60.9 55.817,60.889 55.93,60.795 56.024,60.682 56.035,60.66 56.046,60.682 56.14,60.795 56.253,60.889 56.275,60.9 56.253,60.911 56.14,61.005 56.046,61.118
GND on Bottom (solid): 54.765,61.14 54.754,61.118 54.66,61.005 54.547,60.911 54.525,60.9 54.547,60.889 54.66,60.795 54.754,60.682 54.765,60.66 54.776,60.682 54.87,60.795 54.983,60.889 55.005,60.9 54.983,60.911 54.87,61.005 54.776,61.118
GND on Bottom (solid): 54.765,59.87 54.754,59.848 54.66,59.735 54.547,59.641 54.417,59.572 54.276,59.529 54.13,59.515 53.984,59.529 53.843,59.572 53.713,59.641 53.61,59.726 53.61,59.515 52.983,59.515 52.981,57.265 55.126,59.413 55.126,59.568 55.113,59.572 54.983,59.641 54.87,59.735 54.776,59.848
GND on Bottom (solid): 52.346,56.705 52.346,56.63 52.393,56.677 52.358,56.695
GND on Bottom (solid): 79.921,46.133 79.949,46.081 79.961,46.041 80.237,45.765 80.257,45.763 80.305,45.749

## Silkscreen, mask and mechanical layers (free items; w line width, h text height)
Top Overlay:
  text "3V3 • SWD • 2L" at 37.4,62.9 h0.48
  text "I2C 0x18 • USB-C FS" at 78.4,62.9 h0.5
  text "MSPM0G5117SPMR • NATIVE USB" at 48.4,28.525 h0.52
  text "MCP9808T-E/MS" at 81.4,28.525 h0.55
  text "QUICK CONFIGURE • SENSOR BOARD" at 64.4,27.9 h0.65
